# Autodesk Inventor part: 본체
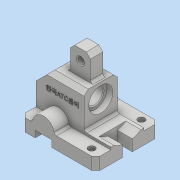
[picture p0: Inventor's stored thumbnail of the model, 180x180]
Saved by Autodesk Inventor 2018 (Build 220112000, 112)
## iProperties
Created: 2022-08
Part Number: 본체
Material: 일반
Document SubType Name: Modeling
Designer: 강의실04
Density: 1 g/cm^3
Appearance: 기본값
Author: 강의실04
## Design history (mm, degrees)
sketch "스케치1"
  geometry: L1 (-45, 38)-(45, 38); L2 (45, 38)-(45, -38); L3 (45, -38)-(-45, -38); L4 (-45, -38)-(-45, 38); 3 further points
  constraints: 8 end point, 2 midpoint, 2 parallel, 1 horizontal, 1 horizontal alignment, 1 perpendicular, 1 vertical alignment
  dimensions: "d0" = 76 distance of L1.end L2.end; "d1" = 90 distance of L1.start L1.end
extrude "돌출1" new body sketch "스케치1" distance "d2" = 15; taper "d3" = 0 deg
sketch "스케치2"
  geometry: L1 (-45, 15)-(45, 15) reference; L2 (45, 15)-(45, 42); L3 (45, 42)-(27, 60); L4 (27, 60)-(-13, 60); L5 (-13, 60)-(-13, 18); L6 (-13, 18)-(-45, 18); L7 (-45, 18)-(-45, 15); L8 (-45, 0)-(-45, 15) reference; 1 further point
  constraints: 12 end point, 3 perpendicular, 2 vertical
  dimensions: "d5" = 45 deg angle of L3 L4; "d6" = 18 distance from line of L3.end L2; "d7" = 32 distance between parallel lines of L8 L5; "d8" = 3 distance of L6.end L1.start; "d22" = 45 distance between parallel lines of L1 L4
extrude "돌출2" join sketch "스케치2" stored distance "d9" = 40; taper "d10" = 0 deg
sketch "스케치3"
  geometry: L1 (27, 60)-(-13, 60) reference; L2 (16, 60)-(16, 90); L3 (16, 90)-(-8, 90); L4 (-8, 90)-(-8, 60); L5 (-13, 60)-(-13, 18) reference; 1 further point
  constraints: 6 end point, 3 perpendicular, 2 point on line
  dimensions: "d11" = 5 distance between parallel lines of L5 L4; "d12" = 24 distance of L2.end L3.end; "d13" = 30 distance between parallel lines of L1 L3
extrude "돌출3" join sketch "스케치3" stored distance "d14" = 15; taper "d15" = 0 deg
chamfer "모따기1" distance "d16" = 5; stored, may be unused: second distance "d17" = 2, angle "d18" = 45 deg
sketch "스케치4"
  geometry: L1 (45, 0)-(-45, 0) reference; L2 (8, 85)-(8, 60) reference; C1 r 4 at (-4, 77); 1 further point
  constraints: 1 centre point
  dimensions: "d23" = 8 diameter of C1; "d24" = 77 distance from line of L1 C1.centre; "d25" = 12 distance from line of C1.centre L2
extrude "돌출4" cut sketch "스케치4" extent not by distance; stored distance "d26" = 15; taper "d27" = 0 deg
node "작업 평면2"
sketch "스케치5"
  geometry: L1 (18, 58)-(18, -18) reference; C1 r 29 at (-24, 20); 2 further points
  constraints: 1 centre point, 1 horizontal alignment, 1 midpoint
  dimensions: "d29" = 58 diameter of C1; "d30" = 42 distance from line of L1 C1.centre
extrude "돌출5" cut sketch "스케치5" distance "d31" = 18; taper "d32" = 0 deg
sketch "스케치6"
  geometry: L1 (-19, 32)-(0, 32); L2 (0, 32)-(0, 44); L3 (0, 44)-(-19, 44); L4 (-19, 44)-(-19, 32); L5 (0, 76)-(0, 0) reference; 3 further points
  constraints: 8 end point, 2 midpoint, 2 parallel, 1 collinear, 1 horizontal, 1 horizontal alignment, 1 perpendicular
  dimensions: "d33" = 12 distance of L1.end L2.end; "d34" = 19 distance of L2.end L3.end
extrude "돌출6" cut sketch "스케치6" distance "d35" = 18; taper "d36" = 0 deg
sketch "스케치7"
  geometry: L1 (0, 15)-(90, 15) reference; L2 (0, 0)-(0, 15) reference; C1 r 13 at (27, 15); 1 further point
  constraints: 1 centre point, 1 point on line
  dimensions: "d37" = 27 distance from line of L2 C1.centre; "d38" = 26 diameter of C1
extrude "돌출7" join sketch "스케치7" stored distance "d39" = 18; taper "d40" = 0 deg
fillet "모깎기1" dims "d41" = 3
sketch "스케치8"
  geometry: L1 (17, 8)-(37, 8); L2 (37, 8)-(37, 0); L3 (37, 0)-(17, 0); L4 (17, 0)-(17, 8); L5 (90, 0)-(0, 0) reference; A1 r 13 centre (27, 15) between (39.769, 17.438) and (14.231, 17.438) reference; 2 further points
  constraints: 8 end point, 2 parallel, 1 collinear, 1 horizontal, 1 midpoint, 1 perpendicular, 1 vertical alignment
  dimensions: "d42" = 20 distance of L2.end L3.end; "d43" = 8 distance of L3.end L1.start
extrude "돌출8" cut sketch "스케치8" extent not by distance; stored distance "d44" = 18; taper "d45" = 0 deg
sketch "스케치9"
  geometry: L1 (45, -38)-(45, -20) reference; L2 (13, -20)-(13, 20) reference; L3 (-2.284, -38)-(45, -38) reference; 2 further points
  dimensions: "d46" = 13 distance from line of L1 point (32, -30); "d47" = 8 distance from line of L3 point (32, -30)
sketch "스케치10"
  geometry: L1 (45, 20)-(45, 38) reference; L2 (45, 38)-(-2.284, 38) reference; 3 further points
  dimensions: "d48" = 13 distance from line of L1 point (32, 30); "d49" = 8 distance from line of point (32, 30) L2
hole "구멍1" sketch "스케치10" at (32, 30), (32, -30) diameter "d50" = 4.5; stored, may be unused: countersink angle "d54" = 90 deg, drill point angle "d56" = 118 deg; dims "d51" = 6, "d52" = 8, "d53" = 4.4, "d55" = 8
sketch "스케치11"
  geometry: L1 (18, 26)-(18, 14) reference; L2 (18, -18)-(18, 58) reference; 3 further points
  constraints: 1 horizontal alignment, 1 midpoint
  dimensions: "d57" = 42 distance from line of L2 point (-24, 20)
hole "구멍2" sketch "스케치11" at (-24, 20) diameter "d58" = 20; stored, may be unused: countersink angle "d62" = 90 deg, drill point angle "d64" = 118 deg; dims "d59" = 6, "d60" = 29, "d61" = 7, "d63" = 8
chamfer "모따기2" distance "d65" = 5; stored, may be unused: second distance "d66" = 2, angle "d67" = 45 deg
sketch "스케치12"
  geometry: L1 (13, 18)-(13, 60) reference; L2 (13, 60)-(-27, 60) reference; 2 further points
  constraints: 1 other
  dimensions: "d68" = 26 distance from line of L1 point (-13, 42); "d69" = 18 distance from line of L2 point (-13, 42)
extrude "돌출9" join sketch "스케치12" distance "d70" = 0.5; taper "d71" = 0 deg
fillet "모깎기2" dims "d72" = 3
fillet "모깎기3" dims "d73" = 3
chamfer "모따기3" distance "d74" = 5; stored, may be unused: second distance "d75" = 2, angle "d76" = 45 deg
chamfer "모따기4" distance "d77" = 1; stored, may be unused: second distance "d78" = 2, angle "d79" = 45 deg
chamfer "모따기5" distance "d80" = 5; stored, may be unused: second distance "d81" = 2, angle "d82" = 45 deg
chamfer "모따기6" distance "d83" = 1; stored, may be unused: second distance "d84" = 2, angle "d85" = 45 deg
chamfer "모따기7" distance "d86" = 1; stored, may be unused: second distance "d87" = 2, angle "d88" = 45 deg
node "솔리드1"
mirror "미러1"
other parameters: "d28" = 32
